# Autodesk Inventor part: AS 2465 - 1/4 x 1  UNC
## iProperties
Comments: To add or edit properties for Autodesk Inventor files, use iProperties.
Created: 2005-06
Part Number: AS 2465 - 1/4 x 1  UNC
Vendor: Autodesk Inc.
Document SubType Name: Modeling
Designer: John Blackburn
Material: Default
Description: Hex Bolt
Standard: AS 2465
Size Designation: 1/4 x 1  UNC
Alert: To add or edit properties for Autodesk Inventor files, use iProperties.
Control State: 0
Master: False
Checked Out: False
Shininess: 64.0
Length Units: 11272
Angle Units: 11279
Time Units: 11290
Mass Units: 11286
Length Display Precision: 3
Angle Display Precision: 2
Compacted: True
EGR: 3
Density: 0.0
Volumn: 0.0
Area: 0.0
PropertySet Name: Model Information
Author: John Blackburn
Revision Number: 8
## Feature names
1. Body [Revolution]
2. Head [Extrusion]
3. Chamfer1 [Revolution]
4. Chamfer2
